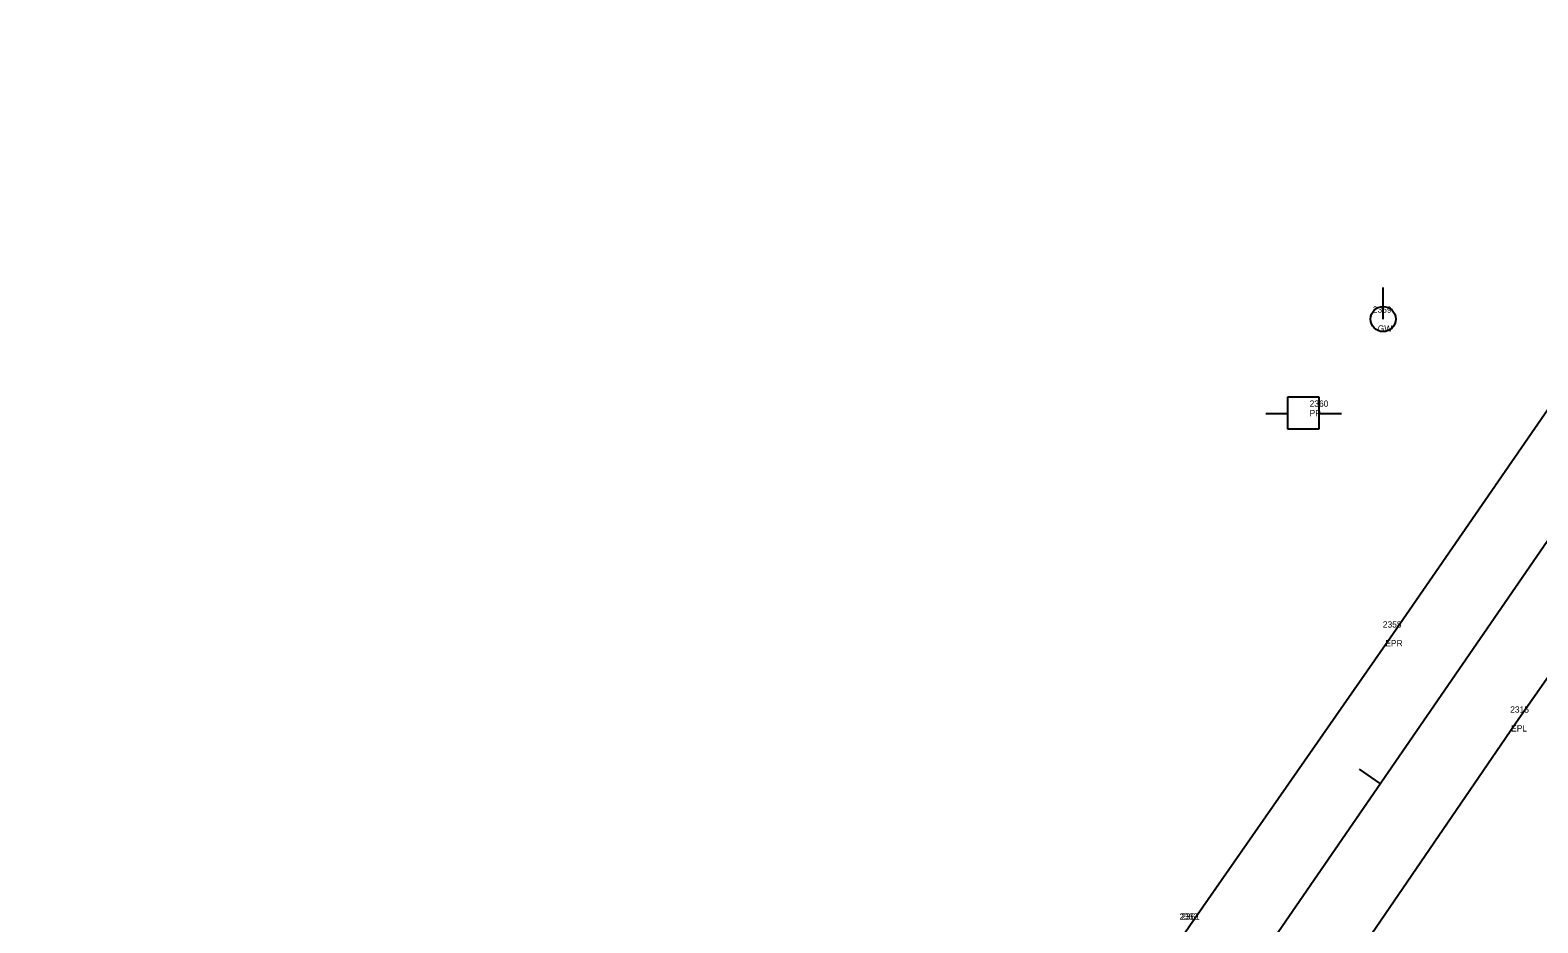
# Model space of a CAD drawing. Extents: x 2266664 to 2272542, y 716533 to 724777.
# Drawn here: x 2271334 to 2271573.7, y 723560.6 to 723702.6 of the extents above; entities that cross this region are included whole.
import ezdxf

# ---------------------------------------------------------------- set-up
doc = ezdxf.new("R2010")
doc.units = 0
for name, color, linetype in [('RD_EX_Road', 7, 'Continuous'), ('RD_EX_Road_txCode', 7, 'Continuous'), ('RD_EX_UT', 7, 'Continuous'), ('RD_EX_UT_txCode', 7, 'Continuous'), ('RD_HC_Cl', 7, 'Continuous'), ('RD_HC_Data_Tic', 7, 'Continuous'), ('RD_SMD_Locator', 7, 'Continuous')]:
    doc.layers.add(name, color=color, linetype=linetype)

msp = doc.modelspace()

# ---------------------------------------------------------------- linework, layer by layer
at = {"layer": 'RD_EX_Road'}
for points in [[(2271604.53, 723684.77), (2271550.65, 723606.61), (2271518.33, 723560.15), (2271484.03, 723509.64), (2271377.45, 723356.07), (2271354.74, 723322.34), (2271292.52, 723232.43), (2271237.2, 723151.69), (2271183.29, 723072.86), (2271144.18, 723016.57), (2271140.21, 723010.22), (2271130.75, 722996.02)], [(2271614.21, 723655.35), (2271570.62, 723593.07), (2271532.38, 723537.1), (2271480.53, 723462.42), (2271443.77, 723408.17), (2271407.1, 723356.2), (2271374.69, 723308.79), (2271312.42, 723217.53), (2271256.65, 723136.94), (2271202.38, 723058.06), (2271164.68, 723002.43), (2271160.3, 722996.7), (2271150.37, 722982.5)]]:
    msp.add_lwpolyline(points, dxfattribs=at)
at = {"layer": 'RD_EX_UT'}
for p, q in [((2271549.06, 723656.67), (2271549.06, 723661.67)), ((2271538.87, 723644.23), (2271533.87, 723644.23)), ((2271533.87, 723644.23), (2271533.87, 723639.23)), ((2271538.87, 723639.23), (2271538.87, 723644.23)), ((2271530.44, 723641.67), (2271533.91, 723641.67)), ((2271538.8, 723641.67), (2271542.44, 723641.67)), ((2271533.87, 723639.23), (2271538.87, 723639.23))]:
    msp.add_line(p, q, dxfattribs=at)
msp.add_circle((2271549.06, 723656.67), 2, dxfattribs=at)
at = {"layer": 'RD_HC_Cl'}
msp.add_line((2267342.91, 717471.2), (2272360.46, 724762.59), dxfattribs=at)
at = {"layer": 'RD_HC_Data_Tic'}
msp.add_line((2271548.61, 723582.83), (2271545.31, 723585.1), dxfattribs=at)
at = {"layer": 'RD_SMD_Locator'}
for centre in [(2271550.65, 723606.61), (2271570.62, 723593.07)]:
    msp.add_circle(centre, 0.001, dxfattribs=at)

# ---------------------------------------------------------------- texts
at = {"layer": 'RD_EX_Road_txCode'}
for s, p in [('2358', (2271549.02, 723607.61)), ('EPR', (2271549.42, 723604.61)), ('2315', (2271569.27, 723594.07)), ('EPL', (2271569.41, 723591.07)), ('2362', (2271516.68, 723561.15)), ('2361', (2271516.96, 723561.15))]:
    msp.add_text(s, height=1, dxfattribs=at).set_placement(p)
at = {"layer": 'RD_EX_UT_txCode'}
for s, p in [('2359', (2271547.43, 723657.67)), ('GW', (2271548.21, 723654.67)), ('2360', (2271537.38, 723642.72)), ('PP', (2271537.38, 723641.22))]:
    msp.add_text(s, height=1, dxfattribs=at).set_placement(p)

doc.saveas('drawing.dxf')
